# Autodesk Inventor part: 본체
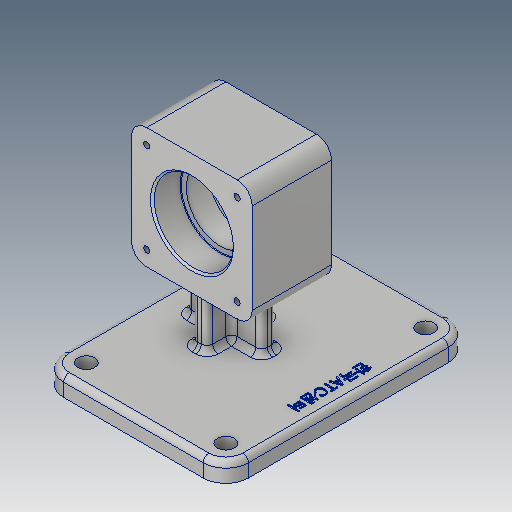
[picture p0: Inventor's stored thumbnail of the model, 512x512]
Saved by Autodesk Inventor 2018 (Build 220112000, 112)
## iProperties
Created: 2020-11
Part Number: 본체
Material: 알루미늄 6061
Document SubType Name: Modeling
Designer: Administrator
Density: 2.7 g/cm^3
Appearance: 알루미늄 - 평지
Mass: 683.214 g
Surface Area: 542.794 cm^2
Volume: 253.042 cm^3
Author: Administrator
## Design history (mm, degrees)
sketch "스케치1"
  geometry: L1 (32, -32)-(-32, -32); L2 (-32, -32)-(-32, 32); L3 (-32, 32)-(32, 32); L4 (32, 32)-(32, -32); L5 (32, -32)-(-32, 32); L6 (-32, -32)-(32, 32); 1 further point
  constraints: 12 end point, 2 midpoint, 2 parallel, 1 horizontal, 1 perpendicular
  dimensions: "d0" = 64 distance of L2.end L3.end; "d1" = 64 distance of L1.end L2.end
extrude "돌출1" new body sketch "스케치1" distance "d2" = 42; taper "d3" = 0 deg
sketch "스케치2"
  geometry: L1 (0, -8.4)-(0, 50.4) reference; L2 (0, 0)-(-21, 0); L3 (-21, 0)-(-21, 15); L4 (-21, 15)-(0, 15); L5 (0, 15)-(0, 0); L6 (0, 15)-(-18, 15); L7 (-18, 15)-(-18, 27); L8 (-18, 27)-(0, 27); L9 (0, 27)-(0, 15); L10 (32, 42)-(-32, 42) reference; L11 (0, 27)-(-21, 27); L12 (-21, 27)-(-21, 42); L13 (-21, 42)-(0, 42); L14 (0, 42)-(0, 27)
  constraints: 24 end point, 6 parallel, 3 horizontal, 3 perpendicular, 2 point on line
  dimensions: "d4" = 15 distance between parallel lines of L4 L2; "d5" = 15 distance between parallel lines of L10 L8; "d6" = 42 diameter of L3 L1; "d7" = 36 diameter of L7 L1
revolve "회전1" sketch "스케치2" stored, may be unused: angle "d8" = 90 deg
fillet "모깎기1" dims "d9" = 0.3
chamfer "모따기1" distance "d10" = 1; stored, may be unused: second distance "d11" = 2, angle "d12" = 45 deg
node "작업 평면1"
sketch "스케치3"
  geometry: L1 (0, 0)-(0, 21); L2 (0, 21)-(-62, 21); L3 (-62, 21)-(-62, 86); L4 (-62, 86)-(36, 86); L5 (36, 86)-(36, -44); L6 (36, -44)-(-62, -44); L7 (-62, -44)-(-62, 21)
  constraints: 14 end point, 3 perpendicular, 1 horizontal, 1 point on line, 1 vertical
  dimensions: "d14" = 21 distance of L1.start L1.end; "d15" = 62 distance of L1.end L2.end; "d16" = 65 distance of L2.end L3.end; "d17" = 98 distance of L3.end L4.end; "d18" = 130 distance of L4.end L5.end; "d19" = 98 distance of L5.end L6.end
extrude "돌출2" join sketch "스케치3" distance "d20" = 10; taper "d21" = 0 deg
sketch "스케치4"
  geometry: L1 (0, -21)-(0, 0); L2 (-20, -25)-(20, -25); L3 (20, -25)-(20, -17); L4 (20, -17)-(-20, -17); L5 (-20, -17)-(-20, -25); L6 (-20, -25)-(20, -17); L7 (20, -25)-(-20, -17); L8 (-4, -38)-(4, -38); L9 (4, -38)-(4, -4); L10 (4, -4)-(-4, -4); L11 (-4, -4)-(-4, -38); L12 (-4, -38)-(4, -4); L13 (4, -38)-(-4, -4)
  constraints: 26 end point, 4 midpoint, 4 parallel, 2 horizontal, 2 perpendicular, 1 vertical
  dimensions: "d22" = 21 distance of L1.start L1.end; "d23" = 8 distance between parallel lines of L11 L9; "d24" = 8 distance between parallel lines of L2 L4; "d25" = 34 distance of L10.end L8.start; "d26" = 40 distance of L2.start L2.end
extrude "돌출3" join sketch "스케치4" stored distance "d27" = 10; taper "d28" = 0 deg
fillet "모깎기2" dims "d29" = 3
fillet "모깎기3" dims "d30" = 12
fillet "모깎기4" dims "d31" = 3
fillet "모깎기5" dims "d32" = 8
sketch "스케치5"
  geometry: L1 (24, -24)-(-24, -24); L2 (-24, -24)-(-24, 24); L3 (-24, 24)-(24, 24); L4 (24, 24)-(24, -24); L5 (24, -24)-(-24, 24); L6 (-24, -24)-(24, 24); 5 further points
  constraints: 12 end point, 4 coincident, 2 midpoint, 2 parallel, 1 horizontal, 1 perpendicular
  dimensions: "d33" = 48 distance of L2.end L3.end; "d34" = 48 distance of L1.end L2.end
hole "구멍1" sketch "스케치5" at (-24, 24), (24, 24), (24, -24), (-24, -24) diameter "d35" = 3.242; stored, may be unused: countersink angle "d39" = 90 deg, drill point angle "d41" = 118 deg; dims "d36" = 8, "d37" = 4, "d38" = 2, "d40" = 10
sketch "스케치6"
  geometry: L1 (24, -24)-(-24, -24); L2 (-24, -24)-(-24, 24); L3 (-24, 24)-(24, 24); L4 (24, 24)-(24, -24); L5 (24, -24)-(-24, 24); L6 (-24, -24)-(24, 24); C1 r 1.621 at (24, 24) reference; C2 r 1.621 at (24, -24) reference; C3 r 1.621 at (-24, -24) reference; 5 further points
  constraints: 12 end point, 4 coincident, 2 midpoint, 2 parallel, 1 horizontal, 1 perpendicular
  dimensions: "d42" = 48 distance of L2.end L3.end; "d43" = 48 distance of L1.end L2.end
hole "구멍2" sketch "스케치6" at (-24, 24), (24, 24), (24, -24), (-24, -24) diameter "d44" = 3.242; stored, may be unused: countersink angle "d48" = 90 deg, drill point angle "d50" = 118 deg; dims "d45" = 8, "d46" = 4, "d47" = 2, "d49" = 10
sketch "스케치7"
  geometry: C1 r 4.5 at (-24, -74); C2 r 4.5 at (-24, 32); C3 r 4.5 at (50, -74); C4 r 4.5 at (50, 32); A1 r 12 centre (-24, -74) between (-36, -74) and (-24, -86) reference; A2 r 12 centre (-24, 32) between (-24, 44) and (-36, 32) reference; A3 r 12 centre (50, -74) between (50, -86) and (62, -74) reference; A4 r 12 centre (50, 32) between (62, 32) and (50, 44) reference; 1 further point
  constraints: 4 centre point, 4 coincident
  dimensions: "d51" = 9 diameter of C1; "d52" = 9 diameter of C2; "d53" = 9 diameter of C3; "d54" = 9 diameter of C4
extrude "돌출4" cut sketch "스케치7" distance "d55" = 10; taper "d56" = 0 deg
sketch "스케치8"
  geometry: L1 (62, -74)-(62, 32) reference; L2 (-24, -86)-(50, -86) reference; 2 further points
  constraints: 1 other
  dimensions: "d57" = 10 distance from line of L1 point (52, -21); "d58" = 65 distance from line of L2 point (52, -21)
feature "엠보싱1" sketch "스케치8" dims "d0" = 64, "d1" = 64, "d59" = 0.5, "d60" = 0
node "솔리드1"
